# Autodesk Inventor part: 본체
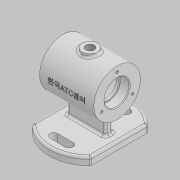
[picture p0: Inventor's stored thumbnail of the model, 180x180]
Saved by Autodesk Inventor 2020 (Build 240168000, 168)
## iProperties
Created: 2021-09
Part Number: 본체
Material: Generic
Document SubType Name: Modeling
Designer: Administrator
Density: 1 g/cm^3
Appearance: Default
Author: Administrator
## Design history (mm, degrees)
sketch "스케치1"
  geometry: L1 (0, 64.27)-(0, -64.27); L2 (37.5, 36.742)-(37.5, -36.742); L3 (-37.5, 36.742)-(-37.5, -36.742); A1 r 52.5 centre (0, 0) between (-37.5, -36.742) and (37.5, -36.742); A2 r 52.5 centre (0, 0) between (37.5, 36.742) and (-37.5, 36.742); 2 further points
  constraints: 6 end point, 4 point on circle, 3 coincident, 2 centre point, 2 parallel, 1 concentric, 1 midpoint, 1 vertical
  dimensions: "d2" = 37.5 distance between parallel lines of L1 L2; "d3" = 75 distance between parallel lines of L2 L3; "d4" = 52.5 radius of A2
extrude "돌출1" new body sketch "스케치1" distance "d5" = 10; taper "d6" = 0 deg
sketch "스케치2"
  geometry: L1 (0, 0)-(0, 127.647); L2 (35, 62)-(-35, 62); L3 (37.5, 0)-(-37.5, 0) reference; L4 (35, 92)-(-35, 92); L5 (20, 87)-(-20, 87); L6 (35, 78)-(23, 78); L7 (35, 92)-(35, 78); L8 (23, 78)-(23, 76); L9 (23, 76)-(20, 76); L10 (20, 87)-(20, 76); L11 (-35, 92)-(-35, 78); L12 (-35, 78)-(-23, 78); L13 (-23, 78)-(-23, 76); L14 (-23, 76)-(-20, 76); L15 (-20, 87)-(-20, 76); 2 further points
  constraints: 28 end point, 4 symmetric about line, 4 vertical, 3 horizontal, 2 midpoint, 2 parallel, 2 vertical alignment
  dimensions: "d7" = 62 distance between parallel lines of L3 L2; "d8" = 70 distance of L2.start L2.end; "d9" = 60 diameter of L4 L2; "d10" = 40 distance of L5.start L5.end; "d11" = 50 diameter of L5 L2; "d12" = 32 diameter of L6 L2; "d13" = 12 distance between parallel lines of L7 L8; "d14" = 28 diameter of L9 L2; "d15" = 3 distance of L8.end L9.end
revolve "회전1" sketch "스케치2" stored, may be unused: angle "d16" = 90 deg
sketch "스케치3"
  geometry: L1 (0, 0)-(0, 37); L2 (-5, 10)-(-5, 37.505); L3 (5, 10)-(5, 37.505); L4 (36.742, 10)-(-36.742, 10) reference; A1 r 25 centre (0, 62) between (-5, 37.505) and (0, 37) reference
  constraints: 6 end point, 3 point on circle, 2 parallel, 2 point on line, 1 vertical
  dimensions: "d17" = 5 distance between parallel lines of L2 L1; "d18" = 10 distance between parallel lines of L3 L2
extrude "돌출2" join sketch "스케치3" stored distance "d19" = 50; taper "d20" = 0 deg
sketch "스케치4"
  geometry: L1 (0, 0)-(0, 116.754); L2 (51.869, 62)-(-50.53, 62); L3 (37.5, 0)-(-37.5, 0) reference; L4 (10, 95)-(0, 95); L5 (10, 95)-(10, 87); L6 (20, 87)-(-20, 87) reference; 1 further point
  constraints: 8 end point, 2 point on line, 2 vertical, 1 horizontal, 1 parallel
  dimensions: "d21" = 62 distance between parallel lines of L2 L3; "d22" = 33 distance between parallel lines of L2 L4; "d25" = 20 diameter of L5 L1
revolve "회전2" sketch "스케치4" stored, may be unused: angle "d26" = 90 deg
sketch "스케치5"
  geometry: C1 r 10 at (0, 0) reference; 2 further points
  constraints: 1 coincident
hole "구멍1" sketch "스케치5" at (0, 0) diameter "d27" = 10.917; stored, may be unused: countersink angle "d31" = 90 deg, drill point angle "d33" = 118 deg; dims "d28" = 24, "d29" = 4, "d30" = 2, "d32" = 29.1
sketch "스케치6" dims "d34" = 46
  geometry: L1 (0, 0)-(-41.654, 0); C1 r 30 at (0, 0) reference; 3 further points
  constraints: 2 end point, 1 coincident, 1 horizontal, 1 horizontal alignment, 1 point on line, 2 other
hole "구멍2" sketch "스케치6" at (-23, 0) diameter "d35" = 3.45873; stored, may be unused: countersink angle "d39" = 90 deg, drill point angle "d41" = 118 deg; dims "d36" = 8, "d37" = 4, "d38" = 2, "d40" = 10
fillet "모깎기1" dims "d45" = 3, "d46" = 0.3
chamfer "모따기1" distance "d47" = 1; stored, may be unused: second distance "d48" = 2, angle "d49" = 45 deg
chamfer "모따기2" distance "d50" = 1; stored, may be unused: second distance "d51" = 2, angle "d52" = 45 deg
fillet "모깎기2" dims "d53" = 3
sketch "스케치7"
  geometry: L1 (0, 79.742)-(0, -79.742); L2 (-10, 79.742)-(-10, -79.742); L3 (10, 79.742)-(10, -79.742); L4 (-77.268, 0)-(77.268, 0); L5 (-77.268, 37)-(77.268, 37); L6 (-77.268, -37)-(77.268, -37); L7 (-10, 42)-(10, 42); L8 (-10, 32)-(10, 32); L9 (-10, -32)-(10, -31.863); L10 (-10, -42)-(10, -42.137); A1 r 5 centre (-10, -37) between (-10, -32) and (-10, -42); A2 r 5.137 centre (10, -37) between (9.93, -42.136) and (9.93, -31.864); A3 r 5 centre (-10, 37) between (-10, 42) and (-10, 32); A4 r 5 centre (10, 37) between (10, 32) and (10, 42); 3 further points
  constraints: 20 end point, 18 point on line, 10 point on circle, 4 centre point, 4 coincident, 4 parallel, 2 midpoint, 1 equal radius, 1 horizontal, 1 vertical
  dimensions: "d54" = 10 distance between parallel lines of L1 L2; "d55" = 20 distance between parallel lines of L2 L3; "d56" = 37 distance between parallel lines of L4 L5; "d57" = 37 distance between parallel lines of L4 L6; "d58" = 10 diameter of A1; "d59" = 10 diameter of A3
extrude "돌출3" cut sketch "스케치7" extent not by distance; stored distance "d60" = 0; taper "d61" = 0 deg
node "작업 평면2"
sketch "스케치9"
  geometry: L1 (-35, 92)-(-35, 32) reference; L2 (35, 92)-(-35, 92) reference; 2 further points
  constraints: 1 other
  dimensions: "d68" = 35 distance from line of point (0, 62) L1; "d69" = 30 distance from line of point (0, 62) L2
feature "엠보싱2" sketch "스케치9" dims "d70" = 0.5, "d71" = 0
node "솔리드1"
pattern_circular "원형 패턴1" dims angle "d43" = 360 deg
mirror "미러1"
feature "A9D066F2-1C7D-4E18-AEED-F7BC21143FA4" dims "d35" = 3.45873, "d36" = 8, "d37" = 4, "d38" = 2, "d39" = 90 deg, "d40" = 10, "d41" = 118 deg
other parameters: "d1" = 105, "d67" = -59.75
